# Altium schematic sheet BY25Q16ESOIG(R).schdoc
size 127 x 101 mm
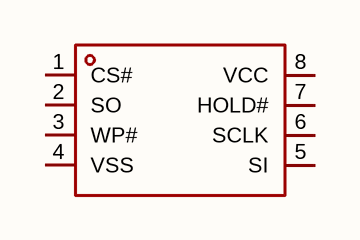
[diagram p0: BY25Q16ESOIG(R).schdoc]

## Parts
U?  by25q16esoig(r)  [TSSOP-8_L4.4-W3.0-P0.65-LS6.4-BL]  (value not drawn)

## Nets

Not connected (* = marked no-connect by the designer): U? 1(CS#) 2(SO) 3(WP#) 4(VSS) 5(SI) 6(SCLK) 7(HOLD#) 8(VCC)

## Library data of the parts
U? = by25q16esoig(r): 接口类型:SPI;存储容量:16Mbit;时钟频率(fc):108MHz;; Manufacturer: BOYAMICRO(博雅); AddInBom: yes; ModelId: 85577802f9634e7e85ffa2fd25a37b6f; ModelName: TSSOP-8_L4.4-W3.0-P0.65-LS6.4-BL-2; ModelTransform: 118.11,251.968,0,0,0,0,0,0,0; Interface: SPI; Memory Size: 16Mbit; Clock Frequency: 108MHz; Voltage - Supply: 2.7V~3.6V; Standby Supply Current: 2.5uA; Program / Erase Cycles: 100000次; Page Programming Time (Tpp): 160us; Data Retention - TDR (Year): 20年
